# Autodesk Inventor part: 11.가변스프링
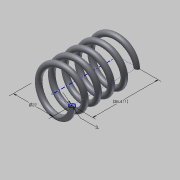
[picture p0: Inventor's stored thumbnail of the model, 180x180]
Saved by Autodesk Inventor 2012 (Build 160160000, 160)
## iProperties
Created: 2014-12
Part Number: 11.가변스프링
Material: 탄소강
Document SubType Name: Modeling
Designer: HOME
Density: 7.87 g/cm^3
Mass: 18.8881 g
Surface Area: 32.5447 cm^2
Volume: 2.40001 cm^3
Author: HOME
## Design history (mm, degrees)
sketch "스케치1"
  geometry: L1 (0, 0)-(11, 0); L2 (11, 0)-(11, 36.411); L3 (11, 36.411)-(0, 36.411); L4 (0, 36.411)-(0, 0); C1 r 1.5 at (11, 0); 1 further point
  constraints: 8 end point, 2 coincident, 2 parallel, 1 centre point, 1 horizontal, 1 perpendicular
  dimensions: "d0" = 22 diameter of L2 L4; "d1" = 36.4112 distance of L1.end L2.end (derived); "d2" = 3 diameter of C1
feature "코일1" pitch "d3" = 10; turns "d5" = 5; dims "d4" = 36.4112 (= d1), "d6" = 0, angle "d7" = 90 deg, angle "d8" = 90 deg, "d9" = 0, "d10" = 0
sketch "스케치2"
  geometry: L1 (-12.5, 0)-(-9.5, 0) reference; 1 further point
  constraints: 1 horizontal alignment
extrude "돌출1" cut sketch "스케치2" stored distance "d11" = 10; taper "d12" = 0 deg
node "작업 평면1"
sketch "스케치3"
  geometry: L1 (-9.5, 0)-(-12.5, 0) reference; 1 further point
  constraints: 1 horizontal alignment
extrude "돌출2" cut sketch "스케치3" stored distance "d13" = 10; taper "d14" = 0 deg
node "솔리드1"
node "절단 모서리 투영1"
node "절단 모서리 투영2"
